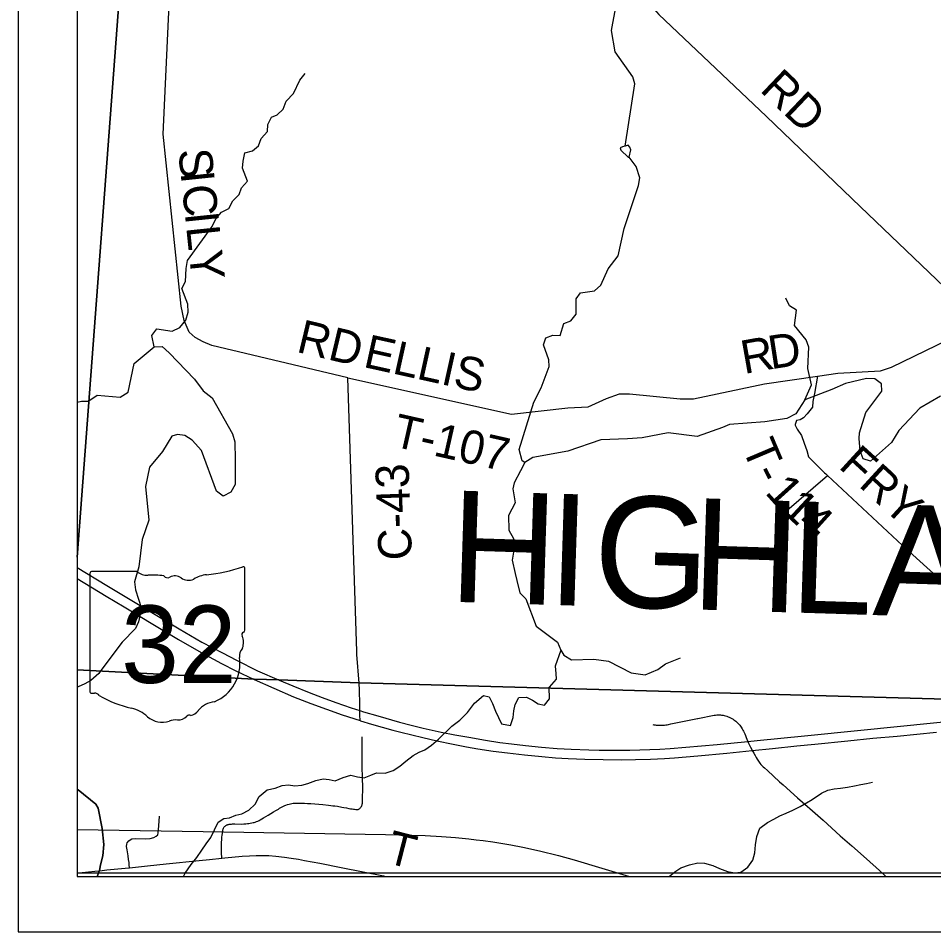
# Model space of a CAD drawing. Extents: x 0 to 34, y 0 to 22.
# Drawn here: x 2 to 3.558, y 14 to 15.554 of the extents above; entities that cross this region are included whole.
import ezdxf

# ---------------------------------------------------------------- set-up
doc = ezdxf.new("R2010")
doc.units = 0
for name, color, linetype in [('Default', 7, 'Continuous'), ('GM_X_County_Road', 7, 'Continuous'), ('GM_X_County_Road_Text', 7, 'Continuous'), ('GM_X_County_Text', 7, 'Continuous'), ('GM_X_Minor_Lake', 7, 'Continuous'), ('GM_X_Minor_River', 7, 'Continuous'), ('GM_X_Rail_Line', 7, 'Continuous'), ('GM_X_State_Location', 7, 'Continuous'), ('GM_X_State_Route', 7, 'Continuous'), ('GM_X_State_Shield', 7, 'Continuous'), ('GM_X_Township_Road', 7, 'Continuous'), ('GM_X_Township_Road_Text', 7, 'Continuous'), ('SH_Cut_Line', 7, 'Continuous'), ('SH_Data', 7, 'Continuous')]:
    doc.layers.add(name, color=color, linetype=linetype)

msp = doc.modelspace()

# ---------------------------------------------------------------- linework, layer by layer
at = {"layer": 'Default'}
for points in [[(2.4006, 20.8941), (2.1, 20.8941), (2.1, 14.637), (2.1837, 15.746), (2.258, 16.7775), (2.2632, 16.8811), (2.2668, 17.0936), (2.2797, 17.8302), (2.3212, 18.6531), (2.3791, 20.1601)], [(2.1, 14.4457), (2.1, 14.243), (2.102, 14.2411), (2.1319, 14.2168), (2.1359, 14.2103), (2.1425, 14.1753), (2.1455, 14.1482), (2.1436, 14.1288), (2.1399, 14.114), (2.1382, 14.1043), (2.1342, 14.0941), (7.3096, 14.0941), (7.3204, 14.3032), (6.8864, 14.3056), (6.7418, 14.3069), (5.4793, 14.3187), (5.0616, 14.3309), (4.9366, 14.3421), (4.819, 14.3535), (4.0144, 14.3862), (3.783, 14.3901), (2.5802, 14.4232), (2.4436, 14.4284), (2.4012, 14.4298)], [(2.1, 14.243), (2.1, 14.0941), (2.1342, 14.0941), (2.1382, 14.1043), (2.1399, 14.114), (2.1436, 14.1288), (2.1455, 14.1482), (2.1425, 14.1753), (2.1359, 14.2103), (2.1319, 14.2168), (2.102, 14.2411)]]:
    msp.add_lwpolyline(points, close=True, dxfattribs=at)
msp.add_lwpolyline([(2.3212, 18.6531), (2.2797, 17.8302), (2.2668, 17.0936), (2.2632, 16.8811), (2.258, 16.7775), (2.1837, 15.746), (2.1, 14.637), (2.1, 14.4457), (2.4012, 14.4298), (2.4436, 14.4284), (2.5802, 14.4232), (3.783, 14.3901), (4.0144, 14.3862), (4.819, 14.3535), (4.9366, 14.3421), (5.2368, 14.8438), (5.4205, 15.1508), (5.9071, 15.964)], dxfattribs=at)
at = {"layer": 'GM_X_County_Road'}
msp.add_line((2.5804, 14.4226), (2.5764, 14.4716), dxfattribs=at)
for points in [[(2.5764, 14.4716), (2.576, 14.4765), (2.5609, 14.9423), (2.3292, 14.9976), (2.3149, 15.0036), (2.301, 15.0111), (2.2909, 15.02), (2.2825, 15.0399), (2.2772, 15.0643), (2.2466, 15.3567), (2.2648, 15.7486), (2.2769, 15.7675), (2.5348, 16.3135), (2.661, 16.5806), (2.7462, 16.7548), (2.8161, 16.9004), (2.88, 17.0272), (2.8992, 17.0651), (2.9226, 17.1033), (2.9413, 17.129), (2.9624, 17.1442), (3.1172, 17.2356), (3.321, 17.3562)], [(2.1891, 14.1089), (2.2198, 14.112), (2.2519, 14.1154), (2.3081, 14.1211), (2.3254, 14.1229), (2.3465, 14.1251)], [(2.3465, 14.1251), (2.3514, 14.1256), (2.381, 14.1284), (2.3934, 14.1292), (2.4046, 14.1296), (2.4169, 14.1297), (2.4262, 14.1294), (2.4385, 14.1285), (2.4533, 14.1268), (2.4643, 14.1253), (2.4771, 14.1231), (2.4869, 14.1213), (2.5131, 14.1163), (2.5497, 14.1092), (2.6216, 14.095), (2.6253, 14.0941)], [(2.1, 14.1), (2.1085, 14.1009), (2.1301, 14.103), (2.1385, 14.1038)], [(2.1385, 14.1038), (2.1505, 14.105), (2.1821, 14.1082), (2.1891, 14.1089)]]:
    msp.add_lwpolyline(points, dxfattribs=at)
at = {"layer": 'GM_X_Minor_Lake'}
for points in [[(3.0399, 15.3178), (3.0424, 15.3303), (3.041, 15.3349), (3.038, 15.338), (3.0327, 15.3366), (3.0281, 15.3351), (3.0246, 15.3337), (3.0257, 15.3295)], [(3.0257, 15.3295), (3.0381, 15.3179), (3.0399, 15.3178)]]:
    msp.add_lwpolyline(points, dxfattribs=at)
at = {"layer": 'GM_X_Minor_River'}
for points in [[(3.0327, 15.3366), (3.0496, 15.4425), (3.046, 15.4547), (3.0157, 15.4969), (3.0095, 15.5331), (3.0119, 15.5455), (3.0228, 15.6034)], [(2.2313, 14.9949), (2.227, 15.0143), (2.2355, 15.0256), (2.2621, 15.0218), (2.275, 15.0277), (2.2851, 15.0404), (2.2891, 15.054), (2.2885, 15.0677), (2.2782, 15.0944), (2.2845, 15.1061), (2.2855, 15.1284), (2.288, 15.1417), (2.3298, 15.1999), (2.3361, 15.2127), (2.3461, 15.2243), (2.3583, 15.2302), (2.3653, 15.2434), (2.3761, 15.2543), (2.3797, 15.2656), (2.3901, 15.2768), (2.3813, 15.2993), (2.3826, 15.3111), (2.3854, 15.3251), (2.3984, 15.3287), (2.4088, 15.3373), (2.4131, 15.3493), (2.4243, 15.3613), (2.4248, 15.3731), (2.4307, 15.3859), (2.4406, 15.3899), (2.451, 15.3993), (2.4561, 15.4132), (2.4684, 15.4259), (2.4794, 15.4489), (2.4882, 15.4602)], [(2.862, 14.7982), (2.8574, 14.8013), (2.8527, 14.8203), (2.8773, 14.9007), (2.8898, 14.9252), (2.9033, 14.9617), (2.9028, 14.9727), (2.8941, 14.9987), (2.8981, 15.0104), (2.9099, 15.0147), (2.9225, 15.0145), (2.9285, 15.0345), (2.9403, 15.0392), (2.9493, 15.0508), (2.9497, 15.0766), (2.9567, 15.0868), (2.9806, 15.0901), (2.9914, 15.0998), (3.0041, 15.128), (3.0211, 15.1501), (3.0314, 15.1962), (3.0554, 15.2698), (3.0579, 15.2826), (3.0518, 15.3017), (3.0399, 15.3178)], [(3.3389, 14.9049), (3.3499, 14.9305), (3.3435, 14.9583), (3.3455, 14.9947), (3.3407, 15.0069), (3.321, 15.0315), (3.3247, 15.0576), (3.3123, 15.065), (3.3064, 15.078)], [(2.1186, 14.9021), (2.1345, 14.9128), (2.1736, 14.9092), (2.187, 14.9181), (2.1972, 14.9669), (2.2313, 14.9949), (2.2446, 14.9955), (2.257, 14.9851), (2.2996, 14.9401), (2.3145, 14.9201), (2.3299, 14.9081), (2.3647, 14.8469), (2.3687, 14.8336), (2.3691, 14.8029), (2.3692, 14.7611), (2.3618, 14.7476), (2.3488, 14.7409), (2.3376, 14.7494), (2.312, 14.8185), (2.2959, 14.8362), (2.2835, 14.8443), (2.271, 14.846), (2.2615, 14.8431), (2.2452, 14.8168), (2.2231, 14.7901), (2.2166, 14.7572), (2.2219, 14.7002), (2.2108, 14.667), (2.2052, 14.6208), (2.1977, 14.5955), (2.1994, 14.5818), (2.2099, 14.5501), (2.2047, 14.5274), (2.1992, 14.5161), (2.1765, 14.4925), (2.1406, 14.4441)], [(3.5694, 14.9114), (3.5346, 14.8907), (3.4987, 14.8525), (3.4863, 14.8322), (3.4502, 14.8005), (3.4377, 14.8045), (3.433, 14.8182), (3.431, 14.8391), (3.4319, 14.8489), (3.4426, 14.8833), (3.4697, 14.9197), (3.4691, 14.9322), (3.4578, 14.9404), (3.4438, 14.9409), (3.4076, 14.9324), (3.3847, 14.9224), (3.3389, 14.9049), (3.3234, 14.8812), (3.3082, 14.8734), (3.2705, 14.8672), (3.2105, 14.8627), (3.1986, 14.8576), (3.1552, 14.8426)], [(2.1186, 14.9021), (2.1076, 14.9019), (2.1, 14.9005)], [(3.1552, 14.8426), (3.1063, 14.849), (3.0618, 14.8401), (3.0371, 14.8386), (2.9912, 14.837), (2.9351, 14.8177), (2.8758, 14.8067), (2.862, 14.7982), (2.8549, 14.7843), (2.844, 14.7639), (2.8416, 14.7533), (2.8455, 14.7298), (2.8345, 14.7083), (2.8346, 14.6832), (2.8427, 14.6687), (2.8444, 14.6558), (2.8403, 14.6323), (2.8457, 14.6095), (2.8485, 14.5973), (2.8536, 14.5764), (2.864, 14.5663), (2.8816, 14.5198), (2.9177, 14.4924), (2.9235, 14.479), (2.9137, 14.4518), (2.915, 14.4393), (2.9153, 14.4294), (2.9033, 14.4159)], [(2.9235, 14.479), (2.9286, 14.4703), (2.9418, 14.4625), (2.9797, 14.4638), (3.0043, 14.4603), (3.043, 14.4403), (3.0669, 14.4372), (3.0887, 14.446), (3.1017, 14.456), (3.1273, 14.4662)], [(2.1406, 14.4441), (2.1371, 14.4391), (2.1233, 14.4275), (2.113, 14.4219), (2.1016, 14.4168), (2.1, 14.4162)], [(2.281, 14.0941), (2.2839, 14.0995), (2.2943, 14.1141), (2.3039, 14.1265), (2.3121, 14.1386), (2.3198, 14.1495), (2.3279, 14.1604), (2.3341, 14.1732), (2.3403, 14.1864), (2.3499, 14.1927), (2.3597, 14.1937), (2.3704, 14.1985), (2.3806, 14.2003), (2.3924, 14.2066), (2.4032, 14.2171), (2.4101, 14.2302), (2.4235, 14.2411), (2.4372, 14.2443), (2.449, 14.2487), (2.46, 14.2497), (2.4709, 14.2484), (2.4823, 14.2494), (2.4929, 14.2519), (2.5066, 14.2571), (2.5188, 14.2599), (2.5293, 14.259), (2.5395, 14.2566), (2.5528, 14.2621), (2.5661, 14.2665), (2.5771, 14.2633), (2.5884, 14.2617), (2.5998, 14.2661), (2.6097, 14.2705), (2.6245, 14.2699), (2.6381, 14.2743), (2.6492, 14.2817), (2.6595, 14.2903), (2.6722, 14.2997), (2.6821, 14.3056), (2.692, 14.3096), (2.7034, 14.3171), (2.7153, 14.3275), (2.7379, 14.3496), (2.7517, 14.3601), (2.7643, 14.3728), (2.7763, 14.3886), (2.7916, 14.4017), (2.8014, 14.3996), (2.8073, 14.3882), (2.8124, 14.3752), (2.8172, 14.3645), (2.8223, 14.3535), (2.8378, 14.3506), (2.8425, 14.3642), (2.8434, 14.3759), (2.8455, 14.3865), (2.8521, 14.3982), (2.8649, 14.3988), (2.8751, 14.3937), (2.8848, 14.3879), (2.8954, 14.3855), (2.9039, 14.396), (2.9033, 14.4159)], [(3.3069, 14.2018), (3.3184, 14.207), (3.3305, 14.2132), (3.3416, 14.2192), (3.3511, 14.2251), (3.3672, 14.2359), (3.3778, 14.2407), (3.3885, 14.2432), (3.3994, 14.2442), (3.4112, 14.2459), (3.4233, 14.2484), (3.4339, 14.2502), (3.4438, 14.252), (3.4537, 14.2545)], [(3.1075, 14.0941), (3.1172, 14.1018), (3.1275, 14.1089), (3.1423, 14.114), (3.1563, 14.1169), (3.1677, 14.1164), (3.182, 14.1128), (3.1937, 14.1077), (3.2069, 14.1022), (3.2193, 14.1001), (3.2295, 14.1011), (3.2418, 14.1097), (3.2499, 14.1217), (3.2538, 14.1342), (3.2548, 14.1475), (3.2568, 14.1622), (3.2623, 14.1762), (3.2749, 14.1859), (3.286, 14.1914), (3.2963, 14.197), (3.3069, 14.2018)]]:
    msp.add_lwpolyline(points, dxfattribs=at)
at = {"layer": 'GM_X_Rail_Line'}
msp.add_lwpolyline([(2.1, 14.1739), (2.3144, 14.1705), (2.6248, 14.1654), (2.6925, 14.1637), (2.7201, 14.1622), (2.7441, 14.1602), (2.7667, 14.158), (2.779, 14.1565), (2.7912, 14.1549), (2.8074, 14.1526), (2.8382, 14.1475), (2.8587, 14.1438), (2.8873, 14.1376), (2.9195, 14.1296), (2.9462, 14.1225), (3.0405, 14.0941)], dxfattribs=at)
at = {"layer": 'GM_X_State_Route'}
for points in [[(2.1, 14.6194), (2.1508, 14.5888), (2.1817, 14.5703), (2.2331, 14.5394), (2.2739, 14.515), (2.3124, 14.4926), (2.3473, 14.4742), (2.3713, 14.4617), (2.407, 14.4439), (2.4439, 14.4278)], [(2.1, 14.6008), (2.1494, 14.571), (2.1804, 14.5526), (2.2317, 14.5216), (2.2725, 14.4973), (2.3111, 14.4749), (2.346, 14.4564), (2.37, 14.4439), (2.4014, 14.4293)], [(2.4014, 14.4293), (2.4685, 14.3996), (2.4978, 14.3884), (2.5511, 14.3689), (2.5816, 14.3592), (2.5825, 14.359), (2.6014, 14.353), (2.6373, 14.3428), (2.6511, 14.3392), (2.6885, 14.3302), (2.7121, 14.3248), (2.7401, 14.3189), (2.7626, 14.3147), (2.7822, 14.3113), (2.808, 14.3074), (2.8326, 14.3042), (2.8616, 14.3008), (2.8912, 14.2978), (2.9141, 14.2959), (2.9358, 14.2946), (2.9644, 14.2935), (2.9954, 14.2927), (3.0258, 14.2924), (3.0506, 14.2927), (3.0761, 14.2935), (3.0996, 14.2946), (3.117, 14.2958), (3.1566, 14.2993), (3.206, 14.304), (3.2491, 14.3084), (3.2839, 14.3118), (3.3253, 14.3161), (3.3556, 14.3192), (3.4119, 14.3248), (3.4546, 14.329), (3.496, 14.3328), (3.5627, 14.3397)], [(2.4439, 14.4278), (2.467, 14.4181), (2.4953, 14.4068), (2.5173, 14.3983), (2.5407, 14.3899), (2.5666, 14.381), (2.5814, 14.3762), (2.5873, 14.3743), (2.6117, 14.3671), (2.6488, 14.3567), (2.6687, 14.3514), (2.6892, 14.3464), (2.7196, 14.3397), (2.7427, 14.335), (2.7666, 14.3307), (2.7954, 14.3257), (2.8197, 14.322), (2.8392, 14.3195), (2.8633, 14.3167), (2.8905, 14.3141), (2.9169, 14.3119), (2.9407, 14.3105), (2.9709, 14.3092), (2.9885, 14.3088), (3.0162, 14.3086), (3.0406, 14.3088), (3.0751, 14.3097), (3.0916, 14.3104), (3.1097, 14.3114), (3.1894, 14.3184), (3.2415, 14.3236), (3.2576, 14.3252), (3.338, 14.3333), (3.434, 14.3431), (3.5576, 14.3555), (3.6924, 14.369)]]:
    msp.add_lwpolyline(points, dxfattribs=at)
at = {"layer": 'GM_X_State_Shield'}
for p, q in [((2.3856, 14.5129), (2.3856, 14.6176)), ((2.1219, 14.6092), (2.1219, 14.4091)), ((2.2018, 14.6126), (2.1245, 14.6126)), ((2.3856, 14.5129), (2.3856, 14.5129))]:
    msp.add_line(p, q, dxfattribs=at)
for centre, radius, start, end in [((2.2917, 14.8855), 0.2796, 275.8445, 288.9065), ((2.3827, 14.618), 0.00294, 351.8621, 97.738), ((2.125, 14.6096), 0.00305, 98.1301, 188.1301), ((2.2201, 14.6359), 0.0296, 231.6195, 271.1119), ((2.23, 14.5003), 0.1064, 80.4867, 94.9883), ((2.2541, 14.6107), 0.00855, 219.7921, 297.1024), ((2.2667, 14.5875), 0.0178, 54.4667, 119.1411), ((2.2896, 14.6193), 0.0214, 233.8562, 294.8282), ((2.3274, 14.5515), 0.0563, 97.3462, 120.7689), ((2.3849, 14.5052), 0.00454, 107.944, 210.337), ((2.3825, 14.5125), 0.00314, 289.6038, 7.7341), ((2.356, 14.492), 0.0273, 340.033, 23.6496), ((2.3961, 14.4691), 0.0198, 136.8065, 186.9296), ((2.3073, 14.4558), 0.0699, 292.3089, 8.9858), ((2.125, 14.4086), 0.00308, 171.9584, 258.3066), ((2.1255, 14.4291), 0.0235, 267.339, 280.6039), ((2.1303, 14.3975), 0.00848, 29.7484, 93.2717), ((2.2373, 14.5773), 0.2019, 240.4129, 257.1985), ((2.1771, 14.3192), 0.0632, 47.1842, 75.836), ((2.3368, 14.3529), 0.0383, 94.4031, 142.5768), ((2.2455, 14.3965), 0.0401, 230.7004, 286.2918), ((2.2716, 14.3816), 0.0214, 268.777, 315.5493), ((2.2909, 14.3622), 0.00601, 65.7517, 132.6484), ((2.2883, 14.3897), 0.0226, 282.8732, 323.2771), ((2.2686, 14.3273), 0.0329, 85.6951, 111.2099)]:
    msp.add_arc(centre, radius, start, end, dxfattribs=at)
at = {"layer": 'GM_X_Township_Road'}
msp.add_line((3.3039, 14.7132), (3.377, 14.776), dxfattribs=at)
for points in [[(3.1089, 15.5997), (3.1076, 15.5982), (3.1001, 15.5922), (3.0941, 15.5874), (3.0864, 15.5796), (3.0829, 15.5732), (3.0824, 15.5695), (3.0899, 15.5602), (3.2729, 15.3876), (3.4334, 15.2332), (3.6407, 15.0353)], [(2.5609, 14.9423), (2.8396, 14.8806), (2.9351, 14.891), (2.9697, 14.8931), (3.0011, 14.9073), (3.0233, 14.9153), (3.0404, 14.915), (3.1265, 14.9063), (3.1489, 14.9066), (3.2701, 14.9322), (3.3601, 14.9452), (3.3946, 14.9501), (3.4676, 14.9541), (3.4863, 14.9603), (3.6407, 15.0353)], [(3.3601, 14.9452), (3.3549, 14.9155), (3.3524, 14.9019), (3.3515, 14.8924), (3.3429, 14.8808), (3.3364, 14.8745), (3.3306, 14.8711), (3.3245, 14.8697), (3.3223, 14.8627)], [(3.3223, 14.8627), (3.3221, 14.8618), (3.3225, 14.8609), (3.3258, 14.8549), (3.3332, 14.8441), (3.3375, 14.8312), (3.3422, 14.8185), (3.3451, 14.8079), (3.3721, 14.7809)], [(3.3721, 14.7809), (3.3742, 14.7789), (3.377, 14.776), (3.505, 14.6573), (3.5641, 14.6039), (3.6123, 14.559), (3.7002, 14.4758), (3.7297, 14.448)], [(2.5814, 14.3762), (2.5812, 14.3871), (2.5807, 14.411), (2.5804, 14.4226)], [(2.5816, 14.3592), (2.5815, 14.3686), (2.5814, 14.3762)], [(3.1557, 14.3627), (3.1567, 14.3629), (3.1845, 14.3684), (3.1865, 14.3686), (3.1888, 14.3688), (3.1906, 14.3689), (3.1928, 14.3689), (3.1949, 14.3687), (3.197, 14.3685), (3.1995, 14.3681), (3.2016, 14.3677), (3.2039, 14.3671), (3.2057, 14.3665), (3.208, 14.3657), (3.2101, 14.3648), (3.2121, 14.3638), (3.2144, 14.3626), (3.2165, 14.3613), (3.218, 14.3603), (3.2197, 14.3591), (3.2212, 14.358), (3.223, 14.3565), (3.2249, 14.3546), (3.2263, 14.353), (3.2279, 14.3511), (3.2291, 14.3496), (3.2303, 14.3479), (3.2322, 14.3449), (3.2334, 14.3428), (3.2343, 14.3409), (3.2353, 14.339), (3.2364, 14.3365), (3.2374, 14.3336), (3.2386, 14.3306), (3.2397, 14.3276), (3.241, 14.3245), (3.2415, 14.3236)], [(3.0802, 14.3526), (3.0819, 14.3522), (3.0838, 14.3519), (3.0859, 14.3516), (3.0878, 14.3515), (3.0899, 14.3513), (3.0923, 14.3512), (3.0949, 14.3512), (3.0974, 14.3513), (3.0997, 14.3515), (3.102, 14.3518), (3.1044, 14.3522), (3.1069, 14.3526), (3.1104, 14.3534), (3.1276, 14.357), (3.1557, 14.3627)], [(2.5855, 14.2817), (2.5855, 14.2827), (2.5855, 14.309), (2.5854, 14.3318)], [(3.2415, 14.3236), (3.2427, 14.3209), (3.2443, 14.3174), (3.2461, 14.3139), (3.2483, 14.3098), (3.2491, 14.3084), (3.2501, 14.3068), (3.2519, 14.3036), (3.2539, 14.3), (3.2557, 14.2966), (3.2576, 14.2933), (3.2597, 14.29), (3.2609, 14.2882), (3.2622, 14.2865), (3.2638, 14.2846), (3.2655, 14.2828), (3.2677, 14.2806), (3.27, 14.2785), (3.2749, 14.274), (3.2955, 14.2551), (3.3015, 14.2497)], [(2.3465, 14.1251), (2.3463, 14.128), (2.3459, 14.1321), (2.3458, 14.1357), (2.3457, 14.1381), (2.3458, 14.1415), (2.3459, 14.1441), (2.3459, 14.1483), (2.3461, 14.152), (2.3463, 14.1566), (2.3466, 14.1607), (2.3468, 14.164), (2.3473, 14.1673), (2.3477, 14.1702), (2.348, 14.1718), (2.3483, 14.1734), (2.3486, 14.1747), (2.3491, 14.176), (2.3497, 14.1772), (2.3505, 14.1782), (2.3512, 14.1789), (2.3518, 14.1795), (2.3525, 14.18), (2.3532, 14.1806), (2.3541, 14.1811), (2.355, 14.1816), (2.3558, 14.1819), (2.3565, 14.1821), (2.3571, 14.1824), (2.3579, 14.1826), (2.3588, 14.1827), (2.3597, 14.1828), (2.3605, 14.183), (2.3615, 14.1831), (2.3629, 14.1832), (2.3644, 14.1833), (2.3655, 14.1833), (2.3684, 14.1833), (2.3796, 14.1832), (2.384, 14.1834), (2.3874, 14.1836), (2.3901, 14.1839), (2.3924, 14.1843), (2.3948, 14.1847), (2.3976, 14.1852), (2.3995, 14.1856), (2.4012, 14.186), (2.4032, 14.1866), (2.4054, 14.1873), (2.4077, 14.1882), (2.4099, 14.1893), (2.4116, 14.1903), (2.4143, 14.1918), (2.4173, 14.1935), (2.4211, 14.1957), (2.4253, 14.1982), (2.4299, 14.201), (2.4344, 14.2037), (2.4383, 14.2061), (2.4405, 14.2074), (2.4427, 14.2087), (2.4447, 14.2099), (2.447, 14.2111), (2.4492, 14.2123), (2.4516, 14.2136), (2.4537, 14.2145), (2.4556, 14.2154), (2.458, 14.2163), (2.461, 14.2172), (2.4631, 14.2177), (2.4653, 14.2181), (2.4678, 14.2184), (2.4703, 14.2187), (2.4734, 14.2188), (2.4767, 14.2189), (2.4802, 14.2188), (2.4836, 14.2187), (2.4869, 14.2185), (2.492, 14.2183), (2.4978, 14.2179), (2.5185, 14.2163), (2.528, 14.2154), (2.5321, 14.2149), (2.5353, 14.2144), (2.5389, 14.2139), (2.5431, 14.2133), (2.5506, 14.212), (2.5543, 14.2113), (2.5586, 14.2105), (2.5625, 14.2098), (2.5654, 14.2093), (2.5682, 14.2088), (2.5705, 14.2085), (2.5724, 14.2082), (2.5745, 14.208), (2.5759, 14.2078), (2.5774, 14.208), (2.5783, 14.2081), (2.5793, 14.2086), (2.58, 14.2089), (2.581, 14.2095), (2.5818, 14.2103), (2.5825, 14.2111), (2.5834, 14.2123), (2.5841, 14.2132), (2.5847, 14.2145), (2.5851, 14.2158), (2.5854, 14.2171), (2.5856, 14.2186), (2.5857, 14.2203), (2.5858, 14.2215), (2.5858, 14.2242), (2.5863, 14.2461), (2.586, 14.2614), (2.5855, 14.2817)], [(3.3015, 14.2497), (3.3262, 14.2278), (3.3385, 14.2171), (3.3516, 14.2056), (3.3698, 14.1896), (3.399, 14.1632), (3.4186, 14.1458), (3.4434, 14.1241), (3.4658, 14.1042), (3.4768, 14.0941)], [(2.1891, 14.1089), (2.1889, 14.1139), (2.1884, 14.1176), (2.1876, 14.1229), (2.1867, 14.129), (2.185, 14.1395), (2.1843, 14.1451), (2.1845, 14.1488), (2.1853, 14.151), (2.188, 14.1545), (2.1901, 14.1563), (2.1932, 14.1579), (2.2003, 14.1588), (2.2162, 14.1578), (2.2247, 14.1585), (2.2307, 14.16), (2.2347, 14.1624), (2.2375, 14.165), (2.2383, 14.168), (2.2391, 14.18), (2.2401, 14.1967)]]:
    msp.add_lwpolyline(points, dxfattribs=at)
at = {"layer": 'SH_Cut_Line'}
msp.add_lwpolyline([(2.4006, 20.8941), (2.1, 20.8941), (2.1, 14.637), (2.1837, 15.746), (2.258, 16.7775), (2.2632, 16.8811), (2.2668, 17.0936), (2.2797, 17.8302), (2.3212, 18.6531), (2.3791, 20.1601)], close=True, dxfattribs=at)
msp.add_lwpolyline([(2.3212, 18.6531), (2.2797, 17.8302), (2.2668, 17.0936), (2.2632, 16.8811), (2.258, 16.7775), (2.1837, 15.746), (2.1, 14.637), (2.1, 14.4457), (2.4012, 14.4298), (2.4436, 14.4284), (2.5802, 14.4232), (3.783, 14.3901), (4.0144, 14.3862), (4.819, 14.3535), (4.9366, 14.3421), (5.0616, 14.3309), (5.4793, 14.3187), (6.7418, 14.3069), (6.8864, 14.3056), (7.3204, 14.3032), (8.6074, 14.2911), (8.7041, 14.2905), (8.9, 14.2922), (8.9, 20.8941)], dxfattribs=at)
at = {"layer": 'SH_Data'}
for p, q in [((2, 21), (2, 14)), ((2.1, 20.9), (2.1, 14.1)), ((2.1, 14.1), (8.9, 14.1)), ((2.1, 14.1), (2.1, 14.1)), ((2, 14), (9, 14))]:
    msp.add_line(p, q, dxfattribs=at)

# ---------------------------------------------------------------- texts
at = {"layer": 'GM_X_County_Road_Text'}
for s, height, rotation, p in [('S', 0.0568, 275.9621, (2.272, 15.3299)), ('I', 0.0568, 275.9611, (2.276, 15.2918)), ('C', 0.0568, 275.9615, (2.2784, 15.2686)), ('I', 0.0568, 275.9623, (2.2833, 15.2222)), ('L', 0.0568, 275.9624, (2.2857, 15.199)), ('Y', 0.0568, 275.9746, (2.2901, 15.1567)), ('RD', 0.05682, 346.5616, (2.4716, 14.9868)), ('C-43', 0.05682, 92.0575, (2.6701, 14.6328)), ('T', 0.0568, 345.5994, (2.6235, 14.1179))]:
    msp.add_text(s, height=height, rotation=rotation, dxfattribs=at).set_placement(p)
at = {"layer": 'GM_X_County_Text'}
for s, rotation, p in [('H', 358.1957, (2.732, 14.5615)), ('I', 358.1948, (2.8994, 14.5563)), ('G', 358.1946, (2.9769, 14.5538)), ('H', 358.1957, (3.1443, 14.5485)), ('L', 358.1946, (3.3117, 14.5433)), ('A', 358.1957, (3.4533, 14.5388))]:
    msp.add_text(s, height=0.1894, rotation=rotation, dxfattribs=at).set_placement(p)
at = {"layer": 'GM_X_State_Location'}
for s in ['s', 'r']:
    msp.add_text(s, height=0.000189, dxfattribs=at).set_placement((2.2508, 14.4958))
msp.add_text('32', height=0.000189, rotation=0, dxfattribs=at).set_placement((2.2031, 14.4821))
at = {"layer": 'GM_X_State_Shield'}
msp.add_text('32', height=0.13184, dxfattribs=at).set_placement((2.1751, 14.4232))
at = {"layer": 'GM_X_Township_Road_Text'}
for s, height, rotation, p in [('RD', 0.05682, 316.3805, (3.2604, 15.431)), ('ELLIS', 0.05682, 347.5523, (2.5854, 14.9611)), ('R', 0.0568, 10.0985, (3.2353, 14.9487)), ('D', 0.0568, 8.7585, (3.2809, 14.9568)), ('T-107', 0.05682, 347.2575, (2.6347, 14.8264)), ('T', 0.0568, 292.9383, (3.2312, 14.8238)), ('FRY', 0.05682, 317.5112, (3.3944, 14.7902)), ('-', 0.0568, 297.0013, (3.2497, 14.7807)), ('1', 0.0568, 311.9692, (3.2694, 14.7466)), ('1', 0.0568, 317.1112, (3.2967, 14.7167)), ('4', 0.0568, 317.8767, (3.3229, 14.6923))]:
    msp.add_text(s, height=height, rotation=rotation, dxfattribs=at).set_placement(p)

doc.saveas('drawing.dxf')
